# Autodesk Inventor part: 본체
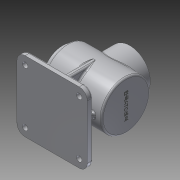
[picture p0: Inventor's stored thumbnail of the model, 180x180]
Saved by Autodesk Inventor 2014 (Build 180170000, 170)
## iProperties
Created: 2015-07
Part Number: 본체
Material: 알루미늄 6061
Document SubType Name: Modeling
Designer: sda
Density: 2.71 g/cm^3
Appearance: 알루미늄 - 평지
Mass: 1276.83 g
Surface Area: 1269.51 cm^2
Volume: 471.154 cm^3
Author: sda
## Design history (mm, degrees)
sketch "스케치1"
  geometry: L1 (0, 0)-(117, 0); L2 (117, 0)-(117, 42); L3 (114, 45)-(10, 45); L4 (7, 42)-(7, 41); L5 (4, 38)-(0, 38); L6 (0, 38)-(0, 28); L7 (1, 27)-(14, 27); L8 (14, 27)-(14, 37); L9 (17, 40)-(107, 40); L10 (110, 37)-(110, 0); L11 (1, 27)-(0, 28); A1 r 3 centre (4, 41) between (4, 38) and (7, 41); A2 r 3 centre (10, 42) between (10, 45) and (7, 42); A3 r 3 centre (17, 37) between (17, 40) and (14, 37); A4 r 3 centre (107, 37) between (110, 37) and (107, 40); A5 r 3 centre (114, 42) between (117, 42) and (114, 45); 2 further points
  constraints: 22 end point, 10 point on circle, 10 tangent, 6 parallel, 5 centre point, 5 point on line, 4 equal radius, 3 perpendicular, 1 horizontal
  dimensions: "d1" = 117 distance of L1.start L1.end; "d2" = 14 distance of point (0, 27) L7.end; "d3" = 117 distance between parallel lines of L2 L6; "d4" = 7 distance of point (7, 38) L5.end; "d5" = 90 diameter of L3 L1; "d6" = 80 diameter of L9 L1; "d7" = 54 diameter of L7 L1; "d8" = 76 diameter of L5 L1; "d9" = 7 distance between parallel lines of L2 L10; "d10" = 3 radius of A1; "d11" = 1 distance of L7.start point (0, 27); "d12" = 45 deg angle of L7 L11
revolve "회전1" sketch "스케치1" stored, may be unused: angle "d13" = 90 deg
node "작업 평면2"
sketch "스케치5"
  geometry: L1 (0, 0)-(0, -78); L2 (0, -78)-(65, -78); L3 (65, -78)-(65, -68); L4 (65, -68)-(-65, -68); L5 (-65, -68)-(-65, -78); L6 (-65, -78)-(0, -78)
  constraints: 12 end point, 2 parallel, 2 perpendicular, 1 vertical
  dimensions: "d34" = 78 distance of L1.start L1.end; "d35" = 65 distance of L1.end L2.end; "d36" = 10 distance of L2.end L3.end; "d37" = 130 distance of L3.end L4.end; "d38" = 10 distance of L4.end L5.end; "d39" = 65 distance of L5.end L1.end (derived)
extrude "돌출2" join sketch "스케치5" stored distance "d40" = 130; taper "d41" = 0 deg
sketch "스케치6"
  geometry: L1 (130, 0)-(0, 0) reference; L2 (0, -130)-(0, 0) reference; L3 (130, -130)-(0, -130) reference; L4 (130, 0)-(130, -130) reference; L5 (0, -65)-(130, -65); L6 (65, 0)-(65, -130); L7 (60, -20)-(70, -20); L8 (70, -20)-(70, -60); L9 (70, -60)-(110, -60); L10 (110, -60)-(110, -70); L11 (110, -70)-(70, -70); L12 (70, -70)-(70, -110); L13 (70, -110)-(60, -110); L14 (60, -110)-(60, -70); L15 (60, -70)-(20, -70); L16 (20, -70)-(20, -60); L17 (20, -60)-(60, -60); L18 (60, -60)-(60, -20); 1 further point
  constraints: 28 end point, 9 parallel, 4 midpoint, 2 perpendicular, 1 collinear
  dimensions: "d42" = 90 distance between parallel lines of L13 L7; "d43" = 45 distance between parallel lines of L5 L7; "d44" = 90 distance between parallel lines of L10 L16; "d45" = 45 distance between parallel lines of L10 L6; "d46" = 10 distance of L15.end L16.end; "d47" = 10 distance of L9.end L10.end; "d48" = 10 distance of L12.end L13.end; "d49" = 10 distance of L7.start L7.end; "d50" = 5 distance between parallel lines of L18 L6; "d51" = 5 distance between parallel lines of L6 L14; "d52" = 5 distance between parallel lines of L5 L15; "d53" = 5 distance between parallel lines of L5 L9
extrude "돌출3" join sketch "스케치6" stored distance "d54" = 130; taper "d55" = 0 deg
fillet "모깎기1" dims "d56" = 15
sketch "스케치7"
  geometry: C1 r 7.5 at (0, -15); C2 r 7.5 at (100, -15); C3 r 7.5 at (100, -115); C4 r 7.5 at (0, -115); A1 r 15 centre (100, -15) between (115, -15) and (100, 0) reference; A2 r 15 centre (0, -15) between (0, 0) and (-15, -15) reference; A3 r 15 centre (0, -115) between (-15, -115) and (0, -130) reference; A4 r 15 centre (100, -115) between (100, -130) and (115, -115) reference; 1 further point
  constraints: 4 centre point, 4 coincident
  dimensions: "d57" = 15 diameter of C1; "d58" = 15 diameter of C2; "d59" = 15 diameter of C3; "d60" = 15 diameter of C4
extrude "돌출4" join sketch "스케치7" distance "d61" = 3; taper "d62" = 0 deg
sketch "스케치8"
  geometry: L1 (-45, -5)-(-45, -45) reference; L2 (-45, -45)-(-5, -45) reference; L3 (-5, -45)-(-5, -55) reference; L4 (-5, -55)-(-45, -55) reference; L5 (-45, -55)-(-45, -95) reference; L6 (-45, -95)-(-55, -95) reference; L7 (-55, -95)-(-55, -55) reference; L8 (-55, -55)-(-95, -55) reference; L9 (-95, -55)-(-95, -45) reference; L10 (-95, -45)-(-55, -45) reference; L11 (-55, -45)-(-55, -5) reference; L12 (-55, -5)-(-45, -5) reference; L13 (0, 15)-(-100, 15) reference; L14 (-115, -100)-(-115, 0) reference; L15 (0, -115)-(-100, -115) reference; L16 (15, 0)-(15, -100) reference; C1 r 7.5 at (0, -100) reference; C2 r 7.5 at (-100, 0) reference; C3 r 7.5 at (0, 0) reference; C4 r 7.5 at (-100, -100) reference; A1 r 15 centre (0, 0) between (15, 0) and (0, 15) reference; A2 r 15 centre (-100, 0) between (-100, 15) and (-115, 0) reference; A3 r 15 centre (-100, -100) between (-115, -100) and (-100, -115) reference; A4 r 15 centre (0, -100) between (0, -115) and (15, -100) reference; 5 further points
  constraints: 4 coincident
hole "구멍1" sketch "스케치8" at (-100, 0), (0, 0), (0, -100), (-100, -100) diameter "d63" = 10; stored, may be unused: countersink angle "d67" = 90 deg, drill point angle "d69" = 118 deg; dims "d64" = 6, "d65" = 4, "d66" = 2, "d68" = 8
sketch "스케치9"
  geometry: C1 r 28 at (0, 0) reference; A1 r 32 centre (0, 0) between (0, 32) and (-32, 0); 2 further points
  constraints: 4 point on circle, 1 centre point, 1 coincident
  dimensions: "d70" = 64 diameter of A1
hole "구멍2" sketch "스케치9" at (0, 32), (-32, 0), (0, -32), (32, 0) diameter "d71" = 3.459; stored, may be unused: countersink angle "d75" = 90 deg, drill point angle "d77" = 118 deg; dims "d72" = 8, "d73" = 4, "d74" = 2, "d76" = 10
node "작업 평면3"
sketch "스케치10"
  geometry: L1 (108.5, -107)-(108.5, -23) reference; L2 (105.5, -110)-(105.5, -20) reference; L3 (108.5, -65)-(53.5, -65); C1 r 38 at (53.5, -65); 1 further point
  constraints: 2 end point, 1 centre point, 1 coincident, 1 midpoint, 1 perpendicular
  dimensions: "d79" = 55 distance of L3.start L3.end; "d80" = 76 diameter of C1
extrude "돌출5" join sketch "스케치10" stored distance "d81" = 3; taper "d82" = 0 deg
hole "구멍3" diameter "d85" = 54; stored, may be unused: countersink angle "d89" = 90 deg, drill point angle "d91" = 0 deg; dims "d83" = 10, "d84" = 10, "d86" = 8, "d87" = 4, "d88" = 2, "d90" = 10
sketch "스케치11"
  geometry: C1 r 38 at (0, 0) reference; A1 r 32 centre (0, 0) between (0, 32) and (32, 0); 3 further points
  constraints: 4 point on circle, 1 centre point, 1 coincident
  dimensions: "d92" = 64 diameter of A1
hole "구멍4" sketch "스케치11" at (0, 32), (32, 0), (0, -32), (-32, 0) diameter "d93" = 3.459; stored, may be unused: countersink angle "d97" = 90 deg, drill point angle "d99" = 118 deg; dims "d94" = 8, "d95" = 4, "d96" = 2, "d98" = 10
chamfer "모따기1" distance "d100" = 1; stored, may be unused: second distance "d101" = 2, angle "d102" = 45 deg
fillet "모깎기2" dims "d103" = 3
fillet "모깎기3" dims "d104" = 3
sketch "스케치12"
  geometry: 1 further point
  constraints: 1 other
feature "엠보싱1" sketch "스케치12" dims "d13" = 90 deg, "d105" = 0.5, "d106" = 0
fillet "모깎기4" dims "d107" = 3
node "솔리드1"
node "투영된 루프1"
node "투영된 루프2"
